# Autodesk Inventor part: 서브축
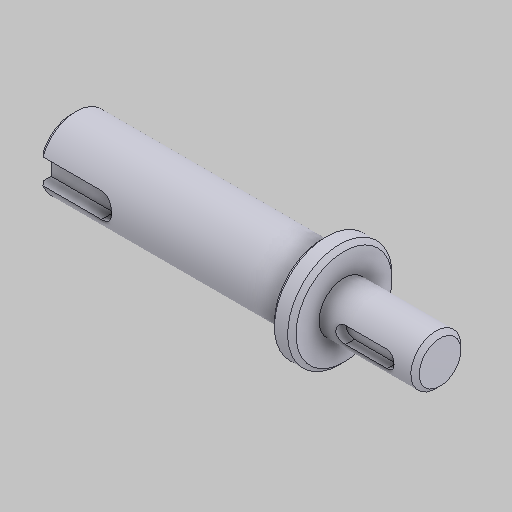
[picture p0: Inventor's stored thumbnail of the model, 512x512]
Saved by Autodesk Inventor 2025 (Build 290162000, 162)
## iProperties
Created: 2024-08
Part Number: 서브축
Material: 강철, 연강
Document SubType Name: Modeling
Designer: 현기
Density: 7.86 g/cm^3
Appearance: 기본값
Author: jhkim
Sending System: Autodesk Inventor 2025
Preprocessor: ST-DEVELOPER v20
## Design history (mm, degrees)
feature "솔리드1"
node "솔리드2"
